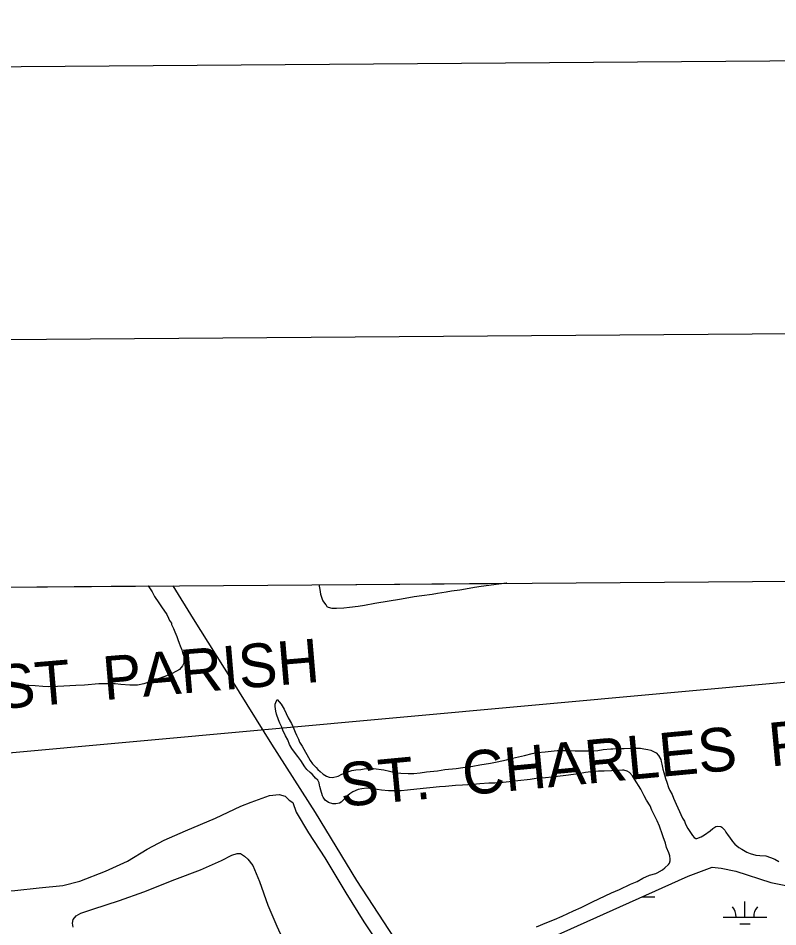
# Model space of a CAD drawing. Extents: x 3535183 to 3573198, y 534952 to 560562.
# Drawn here: x 3557679 to 3559421, y 557896 to 559978 of the extents above; entities that cross this region are included whole.
import ezdxf

# ---------------------------------------------------------------- set-up
doc = ezdxf.new("R2010")
doc.units = 0
for name, color, linetype in [('G-ANNO-NPLT', 7, 'Continuous'), ('V-ANNO-SYMB', 7, 'Continuous'), ('V-GRID-FRAM', 7, 'Continuous'), ('V-RAIL-TRAK', 7, 'Continuous'), ('V-SITE-VEGE', 7, 'Continuous'), ('V-TOPO-BNDY', 7, 'Continuous'), ('V-TOPO-GNAM-IDEN', 7, 'Continuous'), ('V-TOPO-SHOR', 7, 'Continuous'), ('V-WETL-SWMP', 7, 'Continuous')]:
    doc.layers.add(name, color=color, linetype=linetype)

msp = doc.modelspace()

# ---------------------------------------------------------------- linework, layer by layer
at = {"layer": 'G-ANNO-NPLT'}
msp.add_lwpolyline([(3535949.2, 535534.9), (3572614.9, 535812.3), (3572432.1, 559978.2), (3535766.5, 559700.9)], close=True, dxfattribs=at)
at = {"layer": 'V-ANNO-SYMB'}
msp.add_lwpolyline([(3538694.6, 536180.8), (3571776.8, 536431), (3571603.5, 559346.9), (3538521.2, 559096.7), (3538694.6, 536180.8)], dxfattribs=at)
at = {"layer": 'V-GRID-FRAM'}
msp.add_lwpolyline([(3539245.8, 558535.3), (3570887.5, 558774.6), (3571033, 540592.1), (3539375.4, 540352.7), (3539245.8, 558535.3)], dxfattribs=at)
at = {"layer": 'V-RAIL-TRAK'}
msp.add_lwpolyline([(3558033.3, 558677.4), (3558080.6, 558601.4), (3558168, 558462.1), (3558260, 558314.5), (3558359.7, 558158), (3558454.8, 558002.4), (3558553.9, 557850.4), (3558644.9, 557705.2), (3558724.3, 557582.2)], dxfattribs=at)
at = {"layer": 'V-SITE-VEGE'}
for p, q in [((3558370.3, 558680), (3558799.7, 558683.2)), ((3558370.3, 558676.4), (3558370.3, 558680)), ((3558781.3, 558681), (3558740.9, 558675.8)), ((3558798.7, 558683.1), (3558781.3, 558681)), ((3558799.7, 558683.2), (3558798.7, 558683.1)), ((3557636.2, 558674.4), (3557976.9, 558677)), ((3557976.9, 558677), (3557986, 558663.6)), ((3557986, 558663.6), (3557991.7, 558653.2)), ((3558370.8, 558672.8), (3558370.3, 558676.4)), ((3558371.9, 558664.1), (3558370.8, 558672.8)), ((3558372.9, 558657.5), (3558371.9, 558664.1)), ((3558640.8, 558659.9), (3558628.5, 558657.8)), ((3558660.7, 558663), (3558640.8, 558659.9)), ((3558673, 558665), (3558660.7, 558663)), ((3558691.9, 558667.1), (3558673, 558665)), ((3558704.7, 558669.7), (3558691.9, 558667.1)), ((3558725.1, 558673.3), (3558704.7, 558669.7)), ((3558740.9, 558675.8), (3558725.1, 558673.3)), ((3557991.7, 558653.2), (3558001.1, 558638.2)), ((3558375.5, 558650.3), (3558372.9, 558657.5)), ((3558378, 558643.7), (3558375.5, 558650.3)), ((3558385.2, 558633.5), (3558378, 558643.7)), ((3558558, 558647), (3558496.6, 558637.2)), ((3558587.1, 558652.1), (3558558, 558647)), ((3558605, 558654.2), (3558587.1, 558652.1)), ((3558628.5, 558657.8), (3558605, 558654.2)), ((3558001.1, 558638.2), (3558007.3, 558629.4)), ((3558007.3, 558629.4), (3558019.8, 558611.3)), ((3558387.8, 558629.4), (3558385.2, 558633.5)), ((3558390.3, 558627.9), (3558387.8, 558629.4)), ((3558399, 558625.8), (3558390.3, 558627.9)), ((3558408.7, 558625.8), (3558399, 558625.8)), ((3558426.1, 558626.4), (3558408.7, 558625.8)), ((3558438.4, 558627.4), (3558426.1, 558626.4)), ((3558458.3, 558630), (3558438.4, 558627.4)), ((3558473.1, 558632.1), (3558458.3, 558630)), ((3558496.6, 558637.2), (3558473.1, 558632.1)), ((3558019.8, 558611.3), (3558024, 558603.5)), ((3558024, 558603.5), (3558026, 558598.3)), ((3558026, 558598.3), (3558030.2, 558591.6)), ((3558030.2, 558591.6), (3558030.7, 558588.4)), ((3558030.7, 558588.4), (3558034.9, 558579.6)), ((3558034.9, 558579.6), (3558038, 558571.9)), ((3558038, 558571.9), (3558042.7, 558561)), ((3558042.7, 558561), (3558044.8, 558554.2)), ((3558044.8, 558554.2), (3558048.4, 558545.9)), ((3558048.4, 558545.9), (3558050.5, 558539.7)), ((3558050.5, 558539.7), (3558054.1, 558530.9)), ((3558054.1, 558530.9), (3558055.7, 558524.7)), ((3558055.7, 558524.7), (3558058.8, 558515.9)), ((3558058.8, 558515.9), (3558058.8, 558499.8)), ((3558055.7, 558494.1), (3558048.5, 558485.8)), ((3558058.8, 558499.8), (3558055.7, 558494.1)), ((3558030.3, 558475.4), (3558012.7, 558469.1)), ((3558041.7, 558481.6), (3558030.3, 558475.4)), ((3558048.5, 558485.8), (3558041.7, 558481.6)), ((3557863.9, 558452.9), (3557831.2, 558449.7)), ((3557901.2, 558452.9), (3557863.9, 558452.9)), ((3557914.2, 558451.4), (3557901.2, 558452.9)), ((3557935, 558449.9), (3557914.2, 558451.4)), ((3557967.1, 558453), (3557952.6, 558449.9)), ((3557976.4, 558455.6), (3557967.1, 558453)), ((3557990.4, 558460.3), (3557976.4, 558455.6)), ((3558000.3, 558463.9), (3557990.4, 558460.3)), ((3558012.7, 558469.1), (3558000.3, 558463.9)), ((3557703.1, 558449), (3557639.9, 558449)), ((3557717.7, 558448), (3557703.1, 558449)), ((3557735.8, 558446.5), (3557717.7, 558448)), ((3557749.3, 558446), (3557735.8, 558446.5)), ((3557769, 558446.5), (3557749.3, 558446)), ((3557783.5, 558447.6), (3557769, 558446.5)), ((3557811, 558449.2), (3557783.5, 558447.6)), ((3557831.2, 558449.7), (3557811, 558449.2)), ((3557943.8, 558449.4), (3557935, 558449.9)), ((3557952.6, 558449.9), (3557943.8, 558449.4)), ((3558268.4, 558406.4), (3558271, 558413.5)), ((3558271, 558413.5), (3558273, 558417.1)), ((3558273, 558417.1), (3558282.2, 558405.9)), ((3558268.4, 558400.7), (3558268.4, 558406.4)), ((3558269.5, 558390.5), (3558268.4, 558400.7)), ((3558271.5, 558382.9), (3558269.5, 558390.5)), ((3558282.2, 558405.9), (3558288.9, 558395.1)), ((3558288.9, 558395.1), (3558298.1, 558375.2)), ((3558276.2, 558370.6), (3558271.5, 558382.9)), ((3558278.7, 558362.9), (3558276.2, 558370.6)), ((3558298.1, 558375.2), (3558305.8, 558361.9)), ((3558283.3, 558353.7), (3558278.7, 558362.9)), ((3558285.9, 558346.6), (3558283.3, 558353.7)), ((3558305.8, 558361.9), (3558309.4, 558353.3)), ((3558309.4, 558353.3), (3558314.5, 558342)), ((3558292, 558333.3), (3558285.9, 558346.6)), ((3558297.2, 558324.1), (3558292, 558333.3)), ((3558314.5, 558342), (3558317.1, 558334.9)), ((3558317.1, 558334.9), (3558321.7, 558326.2)), ((3558321.7, 558326.2), (3558324.3, 558319)), ((3558301.3, 558313.9), (3558297.2, 558324.1)), ((3558306.4, 558304.7), (3558301.3, 558313.9)), ((3558324.3, 558319), (3558330.4, 558309.8)), ((3558330.4, 558309.8), (3558334, 558303.2)), ((3559068.6, 558304.6), (3559083.4, 558305.7)), ((3559083.4, 558305.7), (3559105.9, 558305.7)), ((3559105.9, 558305.7), (3559114.1, 558304.2)), ((3558315.1, 558292.9), (3558306.4, 558304.7)), ((3558320.2, 558286.3), (3558315.1, 558292.9)), ((3558326.9, 558277.1), (3558320.2, 558286.3)), ((3558334, 558303.2), (3558344.8, 558284.3)), ((3558344.8, 558284.3), (3558348.3, 558277.1)), ((3558812.5, 558282.3), (3558840.1, 558288.5)), ((3558840.1, 558288.5), (3558858, 558293.1)), ((3558858, 558293.1), (3558870.2, 558295.2)), ((3558870.2, 558295.2), (3558887.6, 558297.2)), ((3558887.6, 558297.2), (3558915.2, 558299.8)), ((3558915.2, 558299.8), (3558943.3, 558299.9)), ((3558943.3, 558299.9), (3558956.1, 558298.9)), ((3558956.1, 558298.9), (3558988.8, 558298.9)), ((3558988.8, 558298.9), (3559008.3, 558300)), ((3559008.3, 558300), (3559020.5, 558302)), ((3559020.5, 558302), (3559037.9, 558304.1)), ((3559037.9, 558304.1), (3559043, 558304.1)), ((3559043, 558304.1), (3559063.5, 558304.6)), ((3559063.5, 558304.6), (3559068.6, 558304.6)), ((3559114.1, 558304.2), (3559123.3, 558302.1)), ((3559123.3, 558302.1), (3559129.9, 558301.1)), ((3559129.9, 558301.1), (3559142.2, 558295)), ((3559142.2, 558295), (3559147.8, 558288.9)), ((3559147.8, 558288.9), (3559152.9, 558279.7)), ((3558336.1, 558262.8), (3558326.9, 558277.1)), ((3558348.3, 558277.1), (3558354, 558269.5)), ((3558354, 558269.5), (3558357.6, 558265.4)), ((3558357.6, 558265.4), (3558362.7, 558260.8)), ((3558699, 558261.2), (3558722, 558263.8)), ((3558722, 558263.8), (3558737.9, 558266.9)), ((3558737.9, 558266.9), (3558761.9, 558271)), ((3558761.9, 558271), (3558777.7, 558274.1)), ((3558777.7, 558274.1), (3558798.7, 558278.7)), ((3558798.7, 558278.7), (3558812.5, 558282.3)), ((3559152.9, 558279.7), (3559153.5, 558274.6)), ((3559153.5, 558274.6), (3559155, 558269)), ((3559155, 558269), (3559157.6, 558257.2)), ((3558341.2, 558256.7), (3558336.1, 558262.8)), ((3558348.4, 558249.5), (3558341.2, 558256.7)), ((3558353, 558245.5), (3558348.4, 558249.5)), ((3558357.6, 558240.3), (3558353, 558245.5)), ((3558362.7, 558260.8), (3558366.3, 558256.2)), ((3558366.3, 558256.2), (3558371.4, 558252.1)), ((3558371.4, 558252.1), (3558378.5, 558246)), ((3558378.5, 558246), (3558386.2, 558240.9)), ((3558412.8, 558240.9), (3558421.5, 558245.5)), ((3558421.5, 558245.5), (3558435.3, 558251.2)), ((3558435.3, 558251.2), (3558444.5, 558254.3)), ((3558444.5, 558254.3), (3558453.2, 558255.8)), ((3558453.2, 558255.8), (3558464.9, 558256.8)), ((3558464.9, 558256.8), (3558472.1, 558257.9)), ((3558472.1, 558257.9), (3558484.3, 558258.4)), ((3558484.3, 558258.4), (3558493.5, 558258.4)), ((3558493.5, 558258.4), (3558517.6, 558255.9)), ((3558517.6, 558255.9), (3558530.4, 558252.8)), ((3558530.4, 558252.8), (3558537, 558250.8)), ((3558537, 558250.8), (3558547.2, 558248.8)), ((3558547.2, 558248.8), (3558556.4, 558247.8)), ((3558556.4, 558247.8), (3558573.3, 558247.3)), ((3558573.3, 558247.3), (3558586.1, 558247.3)), ((3558586.1, 558247.3), (3558600.9, 558248.8)), ((3558600.9, 558248.8), (3558615.7, 558250.9)), ((3558615.7, 558250.9), (3558640.3, 558253.5)), ((3558640.3, 558253.5), (3558657.6, 558256.1)), ((3558657.6, 558256.1), (3558683.2, 558258.6)), ((3558683.2, 558258.6), (3558699, 558261.2)), ((3558934.7, 558243.1), (3558903, 558239)), ((3558952.6, 558245.2), (3558934.7, 558243.1)), ((3558963.8, 558246.7), (3558952.6, 558245.2)), ((3558980.2, 558249.3), (3558963.8, 558246.7)), ((3558992, 558251.4), (3558980.2, 558249.3)), ((3559009.8, 558252.9), (3558992, 558251.4)), ((3559022.6, 558252.9), (3559009.8, 558252.9)), ((3559040, 558253.5), (3559022.6, 558252.9)), ((3559051.8, 558254), (3559040, 558253.5)), ((3559065.1, 558255), (3559051.8, 558254)), ((3559067.6, 558255), (3559065.1, 558255)), ((3559075.8, 558253), (3559067.6, 558255)), ((3559080.9, 558249.9), (3559075.8, 558253)), ((3559088.1, 558241.8), (3559080.9, 558249.9)), ((3559157.6, 558257.2), (3559159.6, 558249.5)), ((3559159.6, 558249.5), (3559163.7, 558236.2)), ((3558360.7, 558236.8), (3558357.6, 558240.3)), ((3558365.8, 558231.7), (3558360.7, 558236.8)), ((3558367.3, 558228.6), (3558365.8, 558231.7)), ((3558369.4, 558226), (3558367.3, 558228.6)), ((3558369.9, 558220.9), (3558369.4, 558226)), ((3558386.2, 558240.9), (3558392.4, 558238.9)), ((3558392.4, 558238.9), (3558399.5, 558238.4)), ((3558399.5, 558238.4), (3558412.8, 558240.9)), ((3558722.1, 558221.9), (3558698.1, 558220.3)), ((3558737.4, 558223.4), (3558722.1, 558221.9)), ((3558758.4, 558225), (3558737.4, 558223.4)), ((3558772.2, 558225.5), (3558758.4, 558225)), ((3558791.6, 558226.6), (3558772.2, 558225.5)), ((3558824.8, 558230.7), (3558791.6, 558226.6)), ((3558852.9, 558233.8), (3558824.8, 558230.7)), ((3558867.2, 558235.9), (3558852.9, 558233.8)), ((3558888.2, 558237.4), (3558867.2, 558235.9)), ((3558903, 558239), (3558888.2, 558237.4)), ((3559092.2, 558234.6), (3559088.1, 558241.8)), ((3559107, 558211.1), (3559092.2, 558234.6)), ((3559163.7, 558236.2), (3559166.8, 558227.1)), ((3559166.8, 558227.1), (3559170.4, 558215.3)), ((3558370.9, 558217.4), (3558369.9, 558220.9)), ((3558373, 558209.2), (3558370.9, 558217.4)), ((3558376.6, 558196.4), (3558373, 558209.2)), ((3558446.6, 558205.2), (3558439.4, 558200.6)), ((3558458.3, 558210.3), (3558446.6, 558205.2)), ((3558467, 558212.4), (3558458.3, 558210.3)), ((3558478.8, 558213.4), (3558467, 558212.4)), ((3558502.3, 558210.9), (3558478.8, 558213.4)), ((3558512.5, 558209.4), (3558502.3, 558210.9)), ((3558527.9, 558207.3), (3558512.5, 558209.4)), ((3558538.6, 558207.3), (3558527.9, 558207.3)), ((3558557.5, 558207.9), (3558538.6, 558207.3)), ((3558571.8, 558208.9), (3558557.5, 558207.9)), ((3558608.1, 558213.1), (3558571.8, 558208.9)), ((3558622.9, 558214.6), (3558608.1, 558213.1)), ((3558644.9, 558216.7), (3558622.9, 558214.6)), ((3558659.2, 558217.7), (3558644.9, 558216.7)), ((3558682.2, 558219.8), (3558659.2, 558217.7)), ((3558698.1, 558220.3), (3558682.2, 558219.8)), ((3559114.7, 558196.3), (3559107, 558211.1)), ((3559170.4, 558215.3), (3559173.5, 558208.7)), ((3559173.5, 558208.7), (3559178.6, 558199)), ((3558378.1, 558192.8), (3558376.6, 558196.4)), ((3558383.2, 558186.2), (3558378.1, 558192.8)), ((3558390.4, 558181.1), (3558383.2, 558186.2)), ((3558400.6, 558177.5), (3558390.4, 558181.1)), ((3558420, 558181.6), (3558415.9, 558179.1)), ((3558428.2, 558189.8), (3558420, 558181.6)), ((3558430.2, 558192.9), (3558428.2, 558189.8)), ((3558439.4, 558200.6), (3558430.2, 558192.9)), ((3559120.3, 558186.1), (3559114.7, 558196.3)), ((3559128, 558173.3), (3559120.3, 558186.1)), ((3559178.6, 558199), (3559182.2, 558190.8)), ((3559182.2, 558190.8), (3559187.8, 558177)), ((3558407.3, 558178), (3558400.6, 558177.5)), ((3558415.9, 558179.1), (3558407.3, 558178)), ((3559132.1, 558163.1), (3559128, 558173.3)), ((3559144.4, 558138.6), (3559132.1, 558163.1)), ((3559187.8, 558177), (3559191.9, 558168.3)), ((3559191.9, 558168.3), (3559202.2, 558145.3)), ((3559150.1, 558126.3), (3559144.4, 558138.6)), ((3559202.2, 558145.3), (3559206.8, 558138.2)), ((3559151.6, 558122.2), (3559150.1, 558126.3)), ((3559155.2, 558111), (3559151.6, 558122.2)), ((3559206.8, 558138.2), (3559209.4, 558131.5)), ((3559209.4, 558131.5), (3559214.5, 558121.3)), ((3559214.5, 558121.3), (3559219.1, 558114.1)), ((3559266.1, 558116.3), (3559272.2, 558121.4)), ((3559272.2, 558121.4), (3559278.9, 558126)), ((3559278.9, 558126), (3559283.5, 558126.5)), ((3559283.5, 558126.5), (3559290.6, 558126)), ((3559290.6, 558126), (3559292.7, 558124.5)), ((3559292.7, 558124.5), (3559299.3, 558117.8)), ((3559299.3, 558117.8), (3559301.9, 558112.7)), ((3559158.3, 558101.8), (3559155.2, 558111)), ((3559163.4, 558087.5), (3559158.3, 558101.8)), ((3559219.1, 558114.1), (3559225.2, 558105)), ((3559225.2, 558105), (3559229.3, 558100.4)), ((3559229.3, 558100.4), (3559232.9, 558098.3)), ((3559232.9, 558098.3), (3559235.5, 558098.3)), ((3559235.5, 558098.3), (3559245.2, 558101.9)), ((3559245.2, 558101.9), (3559252.8, 558106.5)), ((3559252.8, 558106.5), (3559266.1, 558116.3)), ((3559301.9, 558112.7), (3559307, 558105.6)), ((3559307, 558105.6), (3559310.6, 558101.5)), ((3559310.6, 558101.5), (3559317.3, 558091.8)), ((3559166, 558077.8), (3559163.4, 558087.5)), ((3559171.1, 558065.5), (3559166, 558077.8)), ((3559317.3, 558091.8), (3559322.4, 558085.7)), ((3559322.4, 558085.7), (3559331.6, 558078)), ((3559331.6, 558078), (3559338.3, 558073.9)), ((3559173.7, 558058.4), (3559171.1, 558065.5)), ((3559174.2, 558050.7), (3559173.7, 558058.4)), ((3559338.3, 558073.9), (3559350, 558067.3)), ((3559350, 558067.3), (3559357.7, 558063.7)), ((3559357.7, 558063.7), (3559371, 558060.2)), ((3559371, 558060.2), (3559379.7, 558059.7)), ((3559379.7, 558059.7), (3559394, 558058.6)), ((3559394, 558058.6), (3559404.2, 558055.1)), ((3559161.9, 558030.8), (3559170.1, 558038.4)), ((3559170.1, 558038.4), (3559172.7, 558042)), ((3559172.7, 558042), (3559174.2, 558047.1)), ((3559174.2, 558047.1), (3559174.2, 558050.7)), ((3559404.2, 558055.1), (3559414.4, 558051)), ((3559414.4, 558051), (3559423.1, 558045.9)), ((3559111.4, 558007.2), (3559127.2, 558014.3)), ((3559127.2, 558014.3), (3559141.5, 558018.5)), ((3559141.5, 558018.5), (3559144.1, 558020)), ((3559144.1, 558020), (3559156.3, 558026.7)), ((3559156.3, 558026.7), (3559161.9, 558030.8)), ((3559057.7, 557981.5), (3559083.3, 557993.8)), ((3559083.3, 557993.8), (3559098.6, 558000)), ((3559098.6, 558000), (3559111.4, 558007.2)), ((3558996.4, 557953.4), (3559039.8, 557973.9)), ((3559039.8, 557973.9), (3559057.7, 557981.5)), ((3558969.9, 557940.5), (3558996.4, 557953.4)), ((3558926.9, 557920.6), (3558952.5, 557932.3)), ((3558952.5, 557932.3), (3558969.9, 557940.5)), ((3558891.7, 557905.7), (3558909.1, 557912.9)), ((3558909.1, 557912.9), (3558926.9, 557920.6)), ((3558867.7, 557895.9), (3558891.7, 557905.7))]:
    msp.add_line(p, q, dxfattribs=at)
at = {"layer": 'V-TOPO-BNDY'}
msp.add_line((3554702, 558025.1), (3560298.9, 558535.1), dxfattribs=at)
at = {"layer": 'V-TOPO-SHOR'}
for points in [[(3557395.7, 557929), (3557453.4, 557944.7), (3557503.2, 557955.3), (3557561.3, 557971.5), (3557615.6, 557976.7), (3557671, 557979.5), (3557726.8, 557985.2), (3557781.6, 557990.5), (3557820.5, 558000.5), (3557879.5, 558023.6), (3557929.7, 558046.1), (3557974.8, 558073.9), (3558013.5, 558094.3), (3558062.7, 558115.7), (3558131.5, 558144.9), (3558189.9, 558172.5), (3558213.1, 558181.7), (3558255.4, 558196.7), (3558277.1, 558199.5), (3558291, 558195.7), (3558300.5, 558186.4), (3558309, 558180.6)], [(3558309, 558180.6), (3558316.7, 558159), (3558345.1, 558111), (3558381.9, 558054.3), (3558430, 557974), (3558472, 557907), (3558513.9, 557843.9), (3558546.7, 557793.5), (3558569.5, 557754.9), (3558583, 557739.3), (3558597.2, 557714.3), (3558623.1, 557666.8), (3558645.8, 557631.6), (3558681.2, 557574.8), (3558705, 557533.7), (3558743.3, 557477.4)], [(3557805.1, 557895.5), (3557803.5, 557904.4), (3557804.8, 557912.8), (3557811.6, 557921.3), (3557822.9, 557927.4), (3557849.9, 557936.7), (3557911.4, 557956.3), (3557966.9, 557975.9), (3558038.5, 558004.6), (3558097, 558026.2), (3558145, 558048.1), (3558168.6, 558059.8), (3558180.9, 558063.9), (3558188.8, 558064), (3558197.7, 558058.2), (3558205.7, 558050.9), (3558216.8, 558036.8), (3558232.6, 558000), (3558251.7, 557945.9), (3558272.1, 557897.4), (3558293, 557852.7)]]:
    msp.add_lwpolyline(points, dxfattribs=at)
at = {"layer": 'V-WETL-SWMP'}
for p, q in [((3559215.4, 558012.4), (3559270.5, 558032.6)), ((3559270.5, 558032.6), (3559291.3, 558030.1)), ((3559291.3, 558030.1), (3559324.6, 558023.7)), ((3559324.6, 558023.7), (3559405.2, 557997.2)), ((3558727.6, 557793.7), (3559215.4, 558012.4)), ((3559405.2, 557997.2), (3559553.6, 557967.6)), ((3559108.9, 557964.6), (3559138.9, 557964.6)), ((3559345.7, 557918.2), (3559345.7, 557954.2)), ((3559295.7, 557918.2), (3559395.7, 557918.2)), ((3559333.7, 557902.8), (3559357.7, 557902.8))]:
    msp.add_line(p, q, dxfattribs=at)
for centre, start, end in [((3559290.5, 557918.7), 359.2282, 40.7718), ((3559401, 557918.7), 139.2282, 180.7718)]:
    msp.add_arc(centre, 35.2, start, end, dxfattribs=at)

# ---------------------------------------------------------------- texts
at = {"layer": 'V-TOPO-GNAM-IDEN'}
for s, rotation, p in [('ST.  JOHN THE  BAPTIST  PARISH', 4.855, (3556226, 558275.1)), ('ST.  CHARLES  PARISH', 5.3745, (3558420.7, 558170.6))]:
    msp.add_text(s, height=100, rotation=rotation, dxfattribs=at).set_placement(p)

doc.saveas('drawing.dxf')
